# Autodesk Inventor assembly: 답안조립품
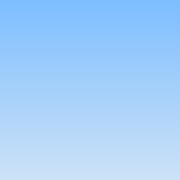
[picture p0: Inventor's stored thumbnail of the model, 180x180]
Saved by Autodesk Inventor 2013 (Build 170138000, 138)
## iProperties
Created: 2016-06
Part Number: 답안조립품
Document SubType Name: Assembly
Designer: Administrator
Author: Administrator
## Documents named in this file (1)
- C:\Users\Administrator\Desktop\460608V1020\답안조립품.iam
